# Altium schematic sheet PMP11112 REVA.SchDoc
size 431 x 558 mm; DocumentNumber: 1; SheetNumber: 1; SheetTotal: 1; PageSetup: Record=PageOptions¦CenterHorizontal=True¦CenterVertical=True¦PrintScale=0.49¦XCorrection=1.00¦YCorrection=1.00¦PrintKind=1¦BorderSize=5000000¦LeftOffset=0¦BottomOffset=0¦Orientation=2¦PaperLength=4318¦PaperWidth=2794¦Scale=100¦PaperSource=15¦PrintQuality=600¦MediaType=1¦DitherType=10¦PrintScaleMode=1¦PaperKind=Tabloid (11 x 17")¦PaperIndex=17
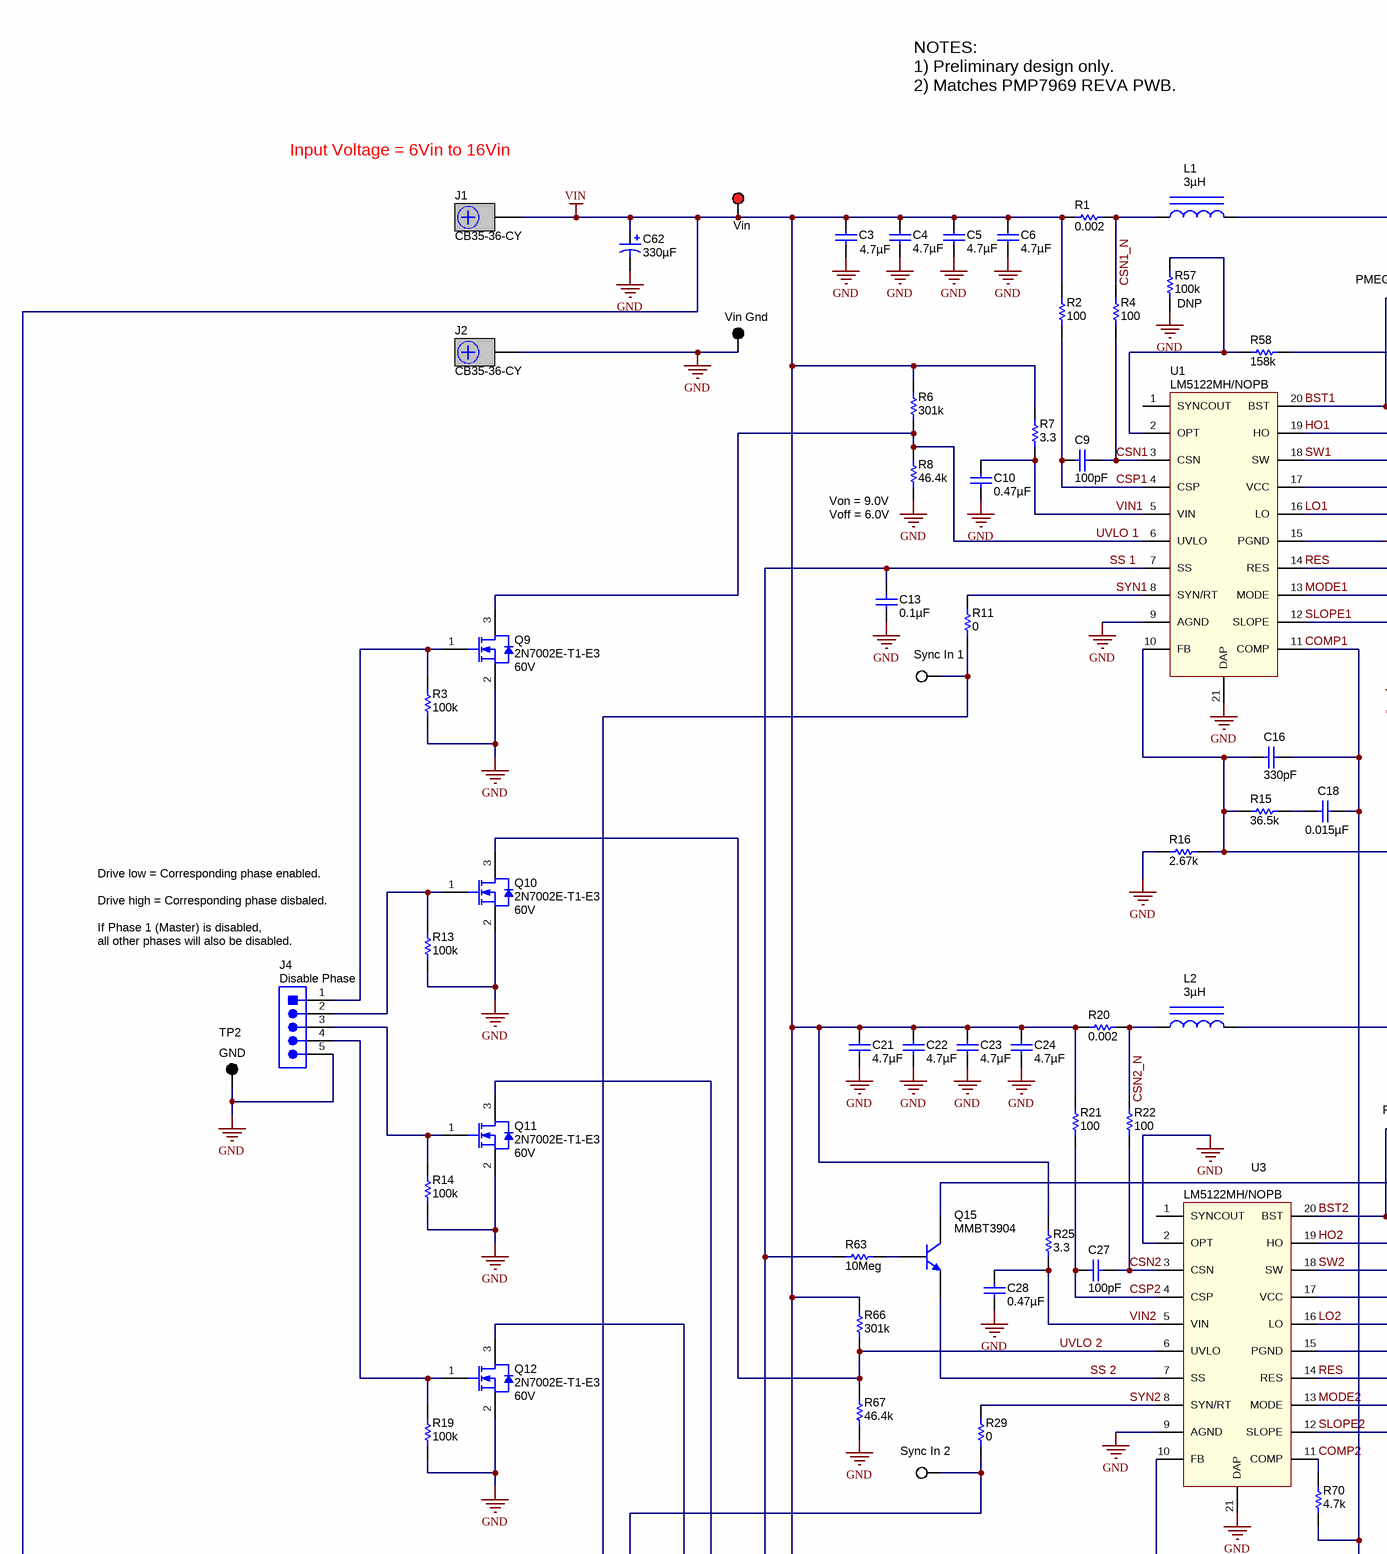
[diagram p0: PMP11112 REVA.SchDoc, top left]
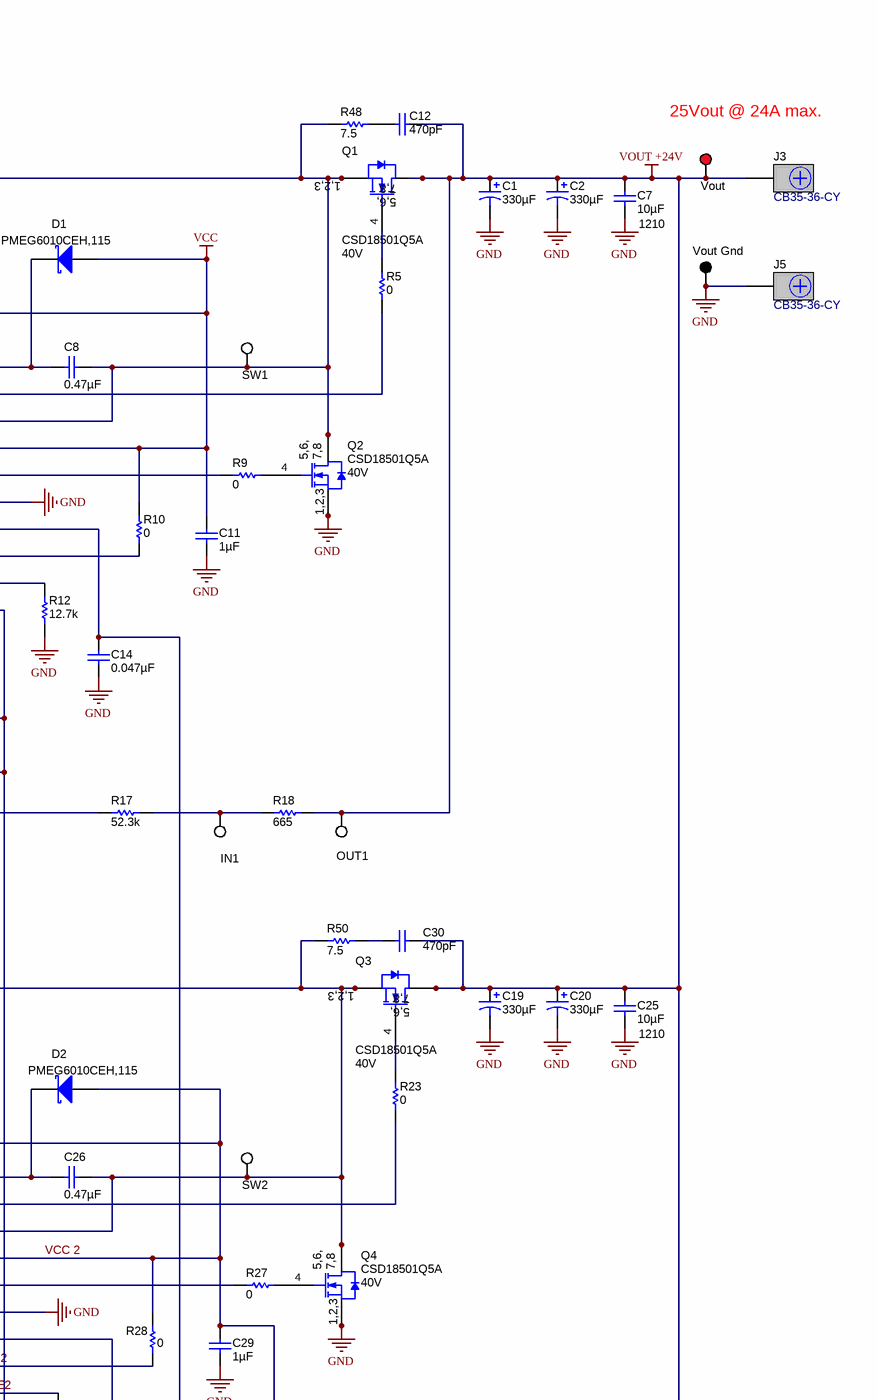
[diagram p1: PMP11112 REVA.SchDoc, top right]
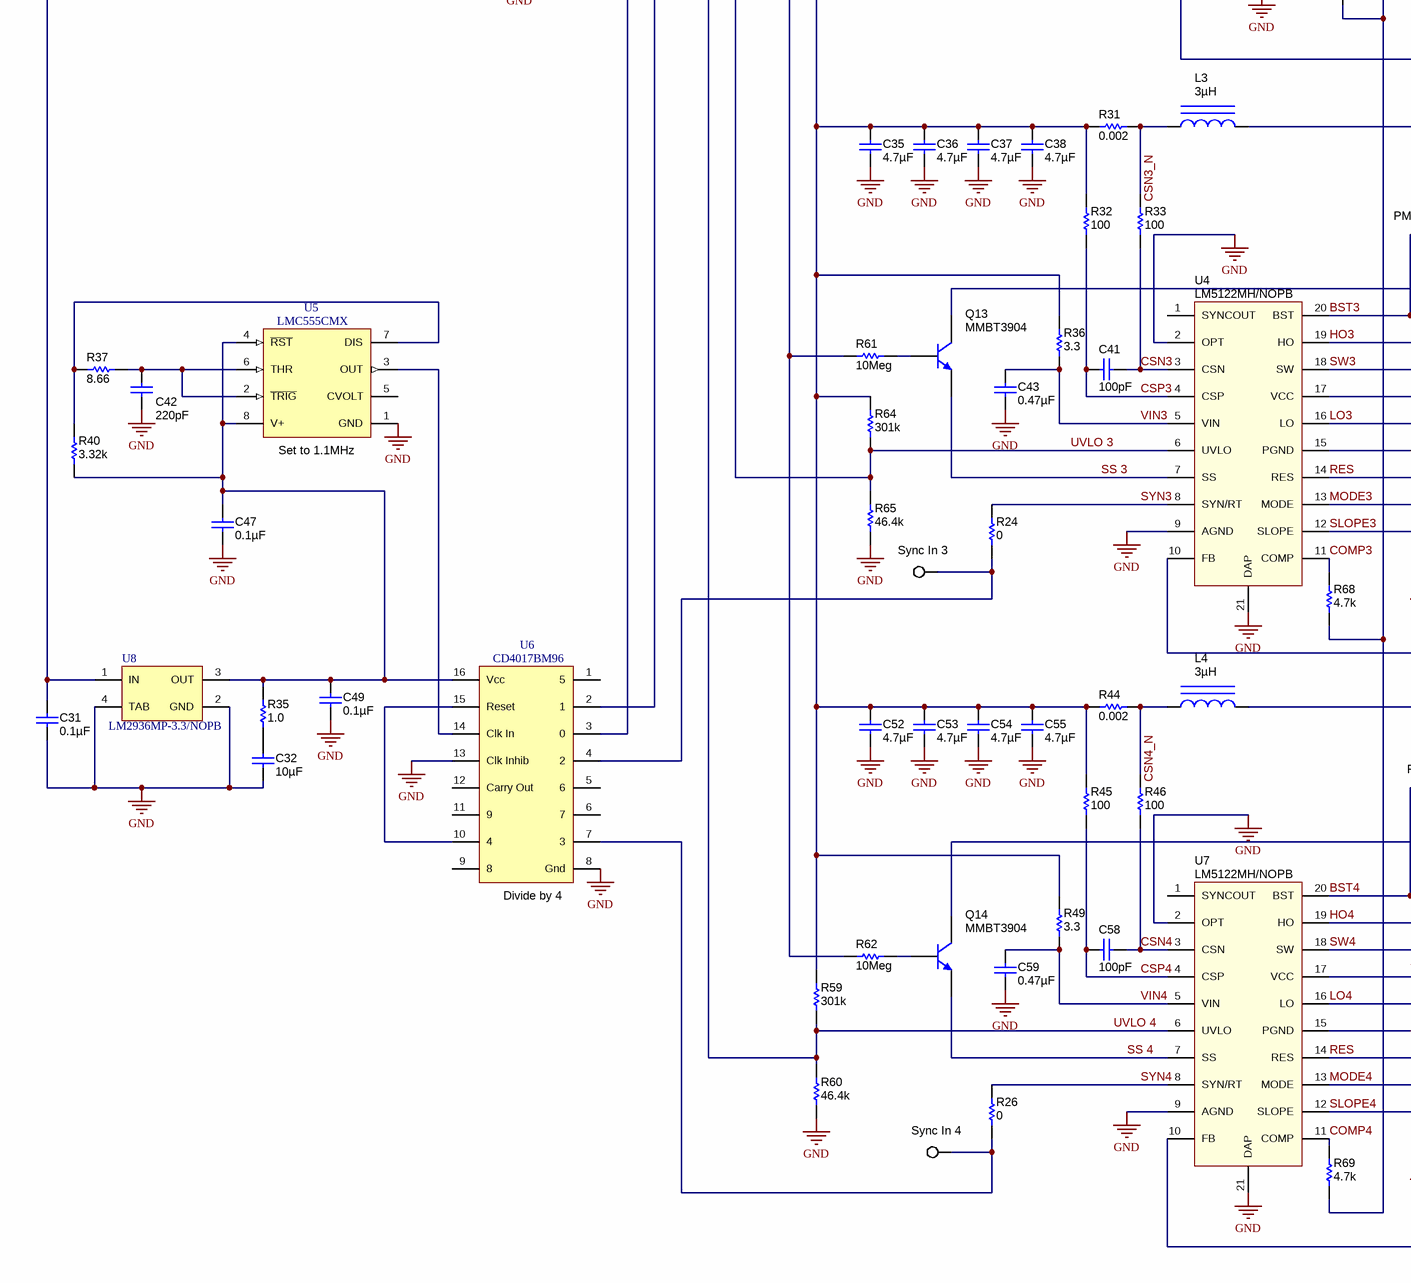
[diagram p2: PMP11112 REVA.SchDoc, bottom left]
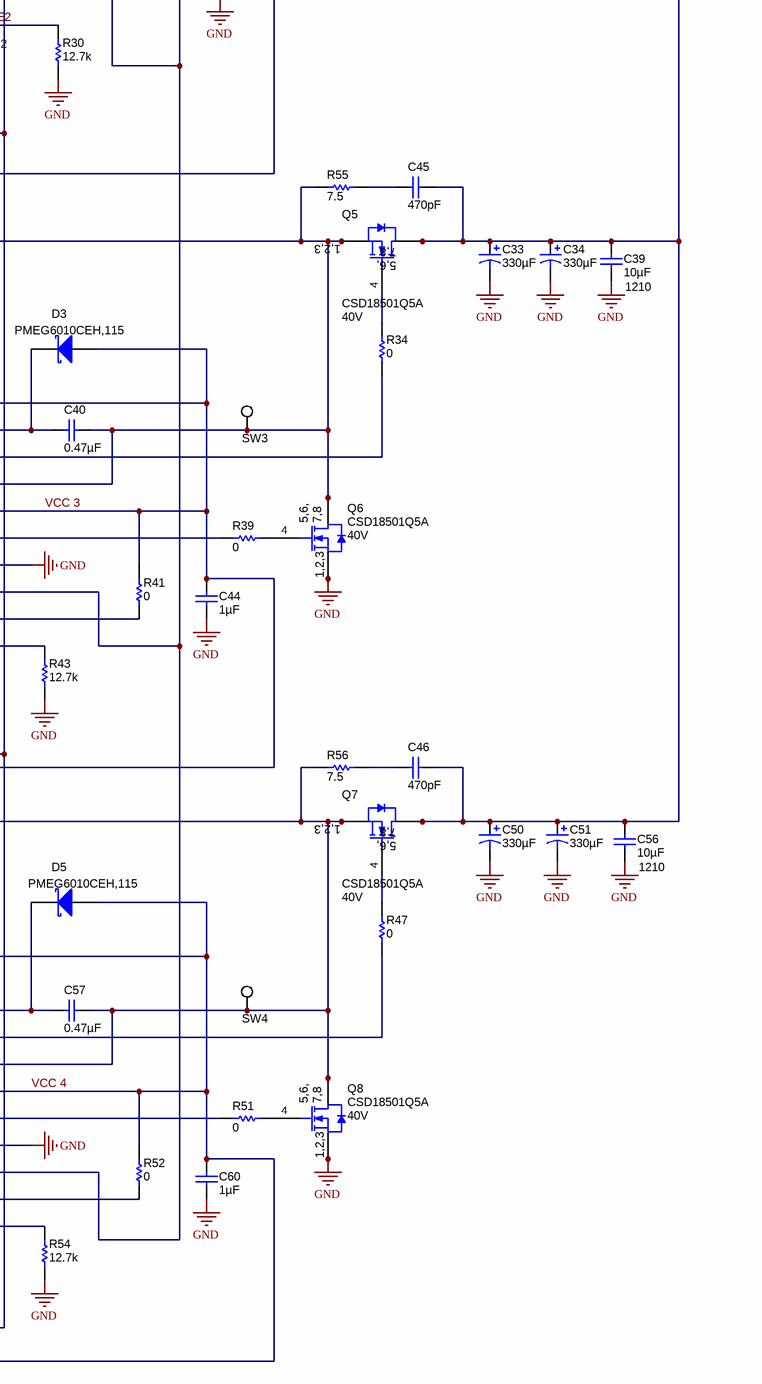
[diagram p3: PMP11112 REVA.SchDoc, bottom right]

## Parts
C1  ValueDisplayed: 330µF  [SM_RADIAL_G]  (hidden comment: EEE-FP1V331AP)
C2  ValueDisplayed: 330µF  [SM_RADIAL_G]  (hidden comment: EEE-FP1V331AP)
C3  ValueDisplayed: 4.7µF  [1206]  (hidden comment: GRM31CR71H475KA12L)
C4  ValueDisplayed: 4.7µF  [1206]  (hidden comment: GRM31CR71H475KA12L)
C5  ValueDisplayed: 4.7µF  [1206]  (hidden comment: GRM31CR71H475KA12L)
C6  ValueDisplayed: 4.7µF  [1206]  (hidden comment: GRM31CR71H475KA12L)
C7  ValueDisplayed: 10µF  [1210]  (hidden comment: GRM32ER7YA106KA12L)
C8  ValueDisplayed: 0.47µF  [0603_HV]  (hidden comment: GRM188R71E474KA12D)
C9  ValueDisplayed: 100pF  [0603_HV]  (hidden comment: GRM1885C1H101JA01D)
C10  ValueDisplayed: 0.47µF  [0603_HV]  (hidden comment: GRM188R71E474KA12D)
C11  ValueDisplayed: 1µF  [0603_HV]  (hidden comment: GRM188R71E105KA12D)
C12  ValueDisplayed: 470pF  [0805_HV]  (hidden comment: GRM2165C2A471JA01D)
C13  ValueDisplayed: 0.1µF  [0603_HV]  (hidden comment: GRM188R71E104KA01D)
C14  ValueDisplayed: 0.047µF  [0603_HV]  (hidden comment: GRM188R71E473KA01D)
C16  ValueDisplayed: 330pF  [0603_HV]  (hidden comment: GRM1885C1H331JA01D)
C18  ValueDisplayed: 0.015µF  [0603_HV]  (hidden comment: C1608X8R2A153K)
C19  ValueDisplayed: 330µF  [SM_RADIAL_G]  (hidden comment: EEE-FP1V331AP)
C20  ValueDisplayed: 330µF  [SM_RADIAL_G]  (hidden comment: EEE-FP1V331AP)
C21  ValueDisplayed: 4.7µF  [1206]  (hidden comment: GRM31CR71H475KA12L)
C22  ValueDisplayed: 4.7µF  [1206]  (hidden comment: GRM31CR71H475KA12L)
C23  ValueDisplayed: 4.7µF  [1206]  (hidden comment: GRM31CR71H475KA12L)
C24  ValueDisplayed: 4.7µF  [1206]  (hidden comment: GRM31CR71H475KA12L)
C25  ValueDisplayed: 10µF  [1210]  (hidden comment: GRM32ER7YA106KA12L)
C26  ValueDisplayed: 0.47µF  [0603_HV]  (hidden comment: GRM188R71E474KA12D)
C27  ValueDisplayed: 100pF  [0603_HV]  (hidden comment: GRM1885C1H101JA01D)
C28  ValueDisplayed: 0.47µF  [0603_HV]  (hidden comment: GRM188R71E474KA12D)
C29  ValueDisplayed: 1µF  [0603_HV]  (hidden comment: GRM188R71E105KA12D)
C30  ValueDisplayed: 470pF  [0805_HV]  (hidden comment: GRM2165C2A471JA01D)
C31  ValueDisplayed: 0.1µF  [0603]  (hidden comment: GCM188R71H104KA57D)
C32  ValueDisplayed: 10µF  [0805_HV]  (hidden comment: GRM21BR71A106KE51L)
C33  ValueDisplayed: 330µF  [SM_RADIAL_G]  (hidden comment: EEE-FP1V331AP)
C34  ValueDisplayed: 330µF  [SM_RADIAL_G]  (hidden comment: EEE-FP1V331AP)
C35  ValueDisplayed: 4.7µF  [1206]  (hidden comment: GRM31CR71H475KA12L)
C36  ValueDisplayed: 4.7µF  [1206]  (hidden comment: GRM31CR71H475KA12L)
C37  ValueDisplayed: 4.7µF  [1206]  (hidden comment: GRM31CR71H475KA12L)
C38  ValueDisplayed: 4.7µF  [1206]  (hidden comment: GRM31CR71H475KA12L)
C39  ValueDisplayed: 10µF  [1210]  (hidden comment: GRM32ER7YA106KA12L)
C40  ValueDisplayed: 0.47µF  [0603_HV]  (hidden comment: GRM188R71E474KA12D)
C41  ValueDisplayed: 100pF  [0603_HV]  (hidden comment: GRM1885C1H101JA01D)
C42  ValueDisplayed: 220pF  [0603]  (hidden comment: C1608C0G1H221J)
C43  ValueDisplayed: 0.47µF  [0603_HV]  (hidden comment: GRM188R71E474KA12D)
C44  ValueDisplayed: 1µF  [0603_HV]  (hidden comment: GRM188R71E105KA12D)
C45  ValueDisplayed: 470pF  [0805_HV]  (hidden comment: GRM2165C2A471JA01D)
C46  ValueDisplayed: 470pF  [0805_HV]  (hidden comment: GRM2165C2A471JA01D)
C47  ValueDisplayed: 0.1µF  [0603_HV]  (hidden comment: GRM188R71E104KA01D)
C49  ValueDisplayed: 0.1µF  [0603_HV]  (hidden comment: GRM188R71E104KA01D)
C50  ValueDisplayed: 330µF  [SM_RADIAL_G]  (hidden comment: EEE-FP1V331AP)
C51  ValueDisplayed: 330µF  [SM_RADIAL_G]  (hidden comment: EEE-FP1V331AP)
C52  ValueDisplayed: 4.7µF  [1206]  (hidden comment: GRM31CR71H475KA12L)
C53  ValueDisplayed: 4.7µF  [1206]  (hidden comment: GRM31CR71H475KA12L)
C54  ValueDisplayed: 4.7µF  [1206]  (hidden comment: GRM31CR71H475KA12L)
C55  ValueDisplayed: 4.7µF  [1206]  (hidden comment: GRM31CR71H475KA12L)
C56  ValueDisplayed: 10µF  [1210]  (hidden comment: GRM32ER7YA106KA12L)
C57  ValueDisplayed: 0.47µF  [0603_HV]  (hidden comment: GRM188R71E474KA12D)
C58  ValueDisplayed: 100pF  [0603_HV]  (hidden comment: GRM1885C1H101JA01D)
C59  ValueDisplayed: 0.47µF  [0603_HV]  (hidden comment: GRM188R71E474KA12D)
C60  ValueDisplayed: 1µF  [0603_HV]  (hidden comment: GRM188R71E105KA12D)
C62  ValueDisplayed: 330µF  [SM_RADIAL_G]  (hidden comment: EEE-FP1V331AP)
D1  PMEG6010CEH,115  [SOD-123F]
D2  PMEG6010CEH,115  [SOD-123F]
D3  PMEG6010CEH,115  [SOD-123F]
D5  PMEG6010CEH,115  [SOD-123F]
IN1  5007  [Keystone5007]  (value not drawn)
J1  CB35-36-CY  [CB35-36-CY]
J2  CB35-36-CY  [CB35-36-CY]
J3  CB35-36-CY  [CB35-36-CY]
J4  Disable Phase  [TSW-105-07-G-S]
J5  CB35-36-CY  [CB35-36-CY]
L1  ValueDisplayed: 3µH  [XAL1580]  (hidden comment: XAL1580-302MEB)
L2  ValueDisplayed: 3µH  [XAL1580]  (hidden comment: XAL1580-302MEB)
L3  ValueDisplayed: 3µH  [XAL1580]  (hidden comment: XAL1580-302MEB)
L4  ValueDisplayed: 3µH  [XAL1580]  (hidden comment: XAL1580-302MEB)
OUT1  5007  [Keystone5007]  (value not drawn)
Q1  CSD18501Q5A  value 40V  [Q5A WITH VIAS]
Q2  CSD18501Q5A  value 40V  [Q5A WITH VIAS]
Q3  CSD18501Q5A  value 40V  [Q5A WITH VIAS]
Q4  CSD18501Q5A  value 40V  [Q5A WITH VIAS]
Q5  CSD18501Q5A  value 40V  [Q5A WITH VIAS]
Q6  CSD18501Q5A  value 40V  [Q5A WITH VIAS]
Q7  CSD18501Q5A  value 40V  [Q5A WITH VIAS]
Q8  CSD18501Q5A  value 40V  [Q5A WITH VIAS]
Q9  2N7002E-T1-E3  value 60V  [SOT-23]
Q10  2N7002E-T1-E3  value 60V  [SOT-23]
Q11  2N7002E-T1-E3  value 60V  [SOT-23]
Q12  2N7002E-T1-E3  value 60V  [SOT-23]
Q13  MMBT3904  [SOT-23]
Q14  MMBT3904  [SOT-23]
Q15  MMBT3904  [SOT-23]
R1  ValueDisplayed: 0.002  [2512]  (hidden comment: CSNL2512FT2L00)
R2  ValueDisplayed: 100  [0603_HV]  (hidden comment: CRCW0603100RFKEA)
R3  value 100k  [0805_HV]  (hidden comment: CRCW0805100KFKEA)
R4  ValueDisplayed: 100  [0603_HV]  (hidden comment: CRCW0603100RFKEA)
R5  value 0  [0603_HV]  (hidden comment: ERJ-3GEY0R00V)
R6  ValueDisplayed: 301k  [0603_HV]  (hidden comment: CRCW0603301KFKEA)
R7  value 3.3  [0603_HV]  (hidden comment: CRCW06033R30JNEA)
R8  ValueDisplayed: 46.4k  [0603]  (hidden comment: RC0603FR-0746K4L)
R9  value 0  [0603_HV]  (hidden comment: ERJ-3GEY0R00V)
R10  value 0  [0603_HV]  (hidden comment: ERJ-3GEY0R00V)
R11  value 0  [0603]  (hidden comment: CRCW06030000Z0EA)
R12  ValueDisplayed: 12.7k  [0603_HV]  (hidden comment: CRCW060312K7FKEA)
R13  value 100k  [0805_HV]  (hidden comment: CRCW0805100KFKEA)
R14  value 100k  [0805_HV]  (hidden comment: CRCW0805100KFKEA)
R15  ValueDisplayed: 36.5k  [0603_HV]  (hidden comment: CRCW060336K5FKEA)
R16  value 2.67k  [0603_HV]  (hidden comment: CRCW06032K67FKEA)
R17  ValueDisplayed: 52.3k  [0805_HV]  (hidden comment: ERJ-6ENF5232V)
R18  ValueDisplayed: 665  [0805_HV]  (hidden comment: CRCW0805665RFKEA)
R19  value 100k  [0805_HV]  (hidden comment: CRCW0805100KFKEA)
R20  ValueDisplayed: 0.002  [2512]  (hidden comment: CSNL2512FT2L00)
R21  ValueDisplayed: 100  [0603_HV]  (hidden comment: CRCW0603100RFKEA)
R22  ValueDisplayed: 100  [0603_HV]  (hidden comment: CRCW0603100RFKEA)
R23  value 0  [0603_HV]  (hidden comment: ERJ-3GEY0R00V)
R24  value 0  [0603]  (hidden comment: CRCW06030000Z0EA)
R25  value 3.3  [0603_HV]  (hidden comment: CRCW06033R30JNEA)
R26  value 0  [0603]  (hidden comment: CRCW06030000Z0EA)
R27  value 0  [0603_HV]  (hidden comment: ERJ-3GEY0R00V)
R28  value 0  [0603_HV]  (hidden comment: ERJ-3GEY0R00V)
R29  value 0  [0603]  (hidden comment: CRCW06030000Z0EA)
R30  ValueDisplayed: 12.7k  [0603_HV]  (hidden comment: CRCW060312K7FKEA)
R31  ValueDisplayed: 0.002  [2512]  (hidden comment: CSNL2512FT2L00)
R32  ValueDisplayed: 100  [0603_HV]  (hidden comment: CRCW0603100RFKEA)
R33  ValueDisplayed: 100  [0603_HV]  (hidden comment: CRCW0603100RFKEA)
R34  value 0  [0603_HV]  (hidden comment: ERJ-3GEY0R00V)
R35  value 1.0  [0603]  (hidden comment: CRCW06031R00JNEA)
R36  value 3.3  [0603_HV]  (hidden comment: CRCW06033R30JNEA)
R37  value 8.66  [0603]  (hidden comment: CRCW06038R66FKEA)
R39  value 0  [0603_HV]  (hidden comment: ERJ-3GEY0R00V)
R40  ValueDisplayed: 3.32k  [0603]  (hidden comment: CRCW06033K32FKEA)
R41  value 0  [0603_HV]  (hidden comment: ERJ-3GEY0R00V)
R43  ValueDisplayed: 12.7k  [0603_HV]  (hidden comment: CRCW060312K7FKEA)
R44  ValueDisplayed: 0.002  [2512]  (hidden comment: CSNL2512FT2L00)
R45  ValueDisplayed: 100  [0603_HV]  (hidden comment: CRCW0603100RFKEA)
R46  ValueDisplayed: 100  [0603_HV]  (hidden comment: CRCW0603100RFKEA)
R47  value 0  [0603_HV]  (hidden comment: ERJ-3GEY0R00V)
R48  value 7.5  [2010M]  (hidden comment: ERJ-12ZYJ7R5U)
R49  value 3.3  [0603_HV]  (hidden comment: CRCW06033R30JNEA)
R50  value 7.5  [2010M]  (hidden comment: ERJ-12ZYJ7R5U)
R51  value 0  [0603_HV]  (hidden comment: ERJ-3GEY0R00V)
R52  value 0  [0603_HV]  (hidden comment: ERJ-3GEY0R00V)
R54  ValueDisplayed: 12.7k  [0603_HV]  (hidden comment: CRCW060312K7FKEA)
R55  value 7.5  [2010M]  (hidden comment: ERJ-12ZYJ7R5U)
R56  value 7.5  [2010M]  (hidden comment: ERJ-12ZYJ7R5U)
R57  DNP  value 100k  [0603]
R58  value 158k  [0603]  (hidden comment: CRCW0603158KFKEA)
R59  ValueDisplayed: 301k  [0603_HV]  (hidden comment: CRCW0603301KFKEA)
R60  ValueDisplayed: 46.4k  [0603]  (hidden comment: RC0603FR-0746K4L)
R61  value 10Meg  [0603]  (hidden comment: CRCW060310M0JNEA)
R62  value 10Meg  [0603]  (hidden comment: CRCW060310M0JNEA)
R63  value 10Meg  [0603]  (hidden comment: CRCW060310M0JNEA)
R64  ValueDisplayed: 301k  [0603_HV]  (hidden comment: CRCW0603301KFKEA)
R65  ValueDisplayed: 46.4k  [0603]  (hidden comment: RC0603FR-0746K4L)
R66  ValueDisplayed: 301k  [0603_HV]  (hidden comment: CRCW0603301KFKEA)
R67  ValueDisplayed: 46.4k  [0603]  (hidden comment: RC0603FR-0746K4L)
R68  value 4.7k  [0603]  (hidden comment: CRCW06034K70JNEA)
R69  value 4.7k  [0603]  (hidden comment: CRCW06034K70JNEA)
R70  value 4.7k  [0603]  (hidden comment: CRCW06034K70JNEA)
SW1  5002  [Keystone5002]  (value not drawn)
SW2  5002  [Keystone5002]  (value not drawn)
SW3  5002  [Keystone5002]  (value not drawn)
SW4  5002  [Keystone5002]  (value not drawn)
Sync_In_1  5007  [Keystone5007]  (value not drawn)
Sync_In_2  5007  [Keystone5007]  (value not drawn)
Sync_In_3  5007  [Keystone5007]  (value not drawn)
Sync_In_4  5007  [Keystone5007]  (value not drawn)
TP2  GND  [Keystone5006]
U1  LM5122MH/NOPB  [MXA20A_L - 10milVia]
U3  LM5122MH/NOPB  [MXA20A_L - 10milVia]
U4  LM5122MH/NOPB  [MXA20A_L - 10milVia]
U5  LMC555CMX  [M08A_N]
U6  CD4017BM96  [D (R-PDSO-G16)]
U7  LM5122MH/NOPB  [MXA20A_L - 10milVia]
U8  LM2936MP-3.3/NOPB  [MP04A_N]
Vin  5000  [Keystone5000]  (value not drawn)
Vin_Gnd  5001  [Keystone5001]  (value not drawn)
Vout  5000  [Keystone5000]  (value not drawn)
Vout_Gnd  5001  [Keystone5001]  (value not drawn)

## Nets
GND: C1.2(-) C2.2(-) C3.2 C4.2 C5.2 C6.2 C7.2 C10.2 C11.2 C13.2 C14.2 C19.2(-) C20.2(-) C21.2 C22.2 C23.2 C24.2 C25.2 C28.2 C29.2 C31.2 C32.2 C33.2(-) C34.2(-) C35.2 C36.2 C37.2 C38.2 C39.2 C42.2 C43.2 C44.2 C47.2 C49.2 C50.2(-) C51.2(-) C52.2 C53.2 C54.2 C55.2 C56.2 C59.2 C60.2 C62.2(-) J2.1 J4.5 J5.1 Q2.1(S) Q2.2(S) Q2.3(S) Q4.1(S) Q4.2(S) Q4.3(S) Q6.1(S) Q6.2(S) Q6.3(S) Q8.1(S) Q8.2(S) Q8.3(S) Q9.2(S) Q10.2(S) Q11.2(S) Q12.2(S) R3.1 R8.1 R12.1 R13.1 R14.1 R16.2 R19.1 R30.1 R43.1 R54.1 R57.1 R60.1 R65.1 R67.1 TP2.1 U1.9(AGND) U1.15(PGND) U1.21(DAP) U3.2(OPT) U3.9(AGND) U3.15(PGND) U3.21(DAP) U4.2(OPT) U4.9(AGND) U4.15(PGND) U4.21(DAP) U5.1(GND) U6.8(Gnd) U6.13(Clk_Inhib) U7.2(OPT) U7.9(AGND) U7.15(PGND) U7.21(DAP) U8.2(GND) U8.4(TAB) Vin_Gnd.1 Vout_Gnd.1
VCC: C11.1 D1.2(A) R10.2 R58.2 U1.17(VCC)
VIN: C3.1 C4.1 C5.1 C6.1 C21.1 C22.1 C23.1 C24.1 C31.1 C35.1 C36.1 C37.1 C38.1 C52.1 C53.1 C54.1 C55.1 C62.1(+) J1.1 R1.1 R2.2 R6.2 R7.2 R20.1 R21.2 R25.2 R31.1 R32.2 R36.2 R44.1 R45.2 R49.2 R59.2 R64.2 R66.2 U8.1(IN) Vin.1
VOUT +24V: C1.1(+) C2.1(+) C7.1 C12.1 C19.1(+) C20.1(+) C25.1 C30.1 C33.1(+) C34.1(+) C39.1 C45.1 C46.1 C50.1(+) C51.1(+) C56.1 J3.1 OUT1.1 Q1.5(D) Q1.6(D) Q1.7(D) Q1.8(D) Q1.9(D) Q3.5(D) Q3.6(D) Q3.7(D) Q3.8(D) Q3.9(D) Q5.5(D) Q5.6(D) Q5.7(D) Q5.8(D) Q5.9(D) Q7.5(D) Q7.6(D) Q7.7(D) Q7.8(D) Q7.9(D) R18.1 Vout.1
BST1: C8.2 D1.1(K) U1.20(BST)
BST2: C26.2 D2.1(K) U3.20(BST)
BST3: C40.2 D3.1(K) U4.20(BST)
BST4: C57.2 D5.1(K) U7.20(BST)
COMP1: C16.2 C18.2 R68.1 R69.1 R70.1 U1.11(COMP)
COMP2: R70.2 U3.11(COMP)
COMP3: R68.2 U4.11(COMP)
COMP4: R69.2 U7.11(COMP)
CSN1: C9.1 R4.1 U1.3(CSN)
CSN1_N: L1.1 R1.2 R4.2
CSN2: C27.1 R22.1 U3.3(CSN)
CSN2_N: L2.1 R20.2 R22.2
CSN3: C41.1 R33.1 U4.3(CSN)
CSN3_N: L3.1 R31.2 R33.2
CSN4: C58.1 R46.1 U7.3(CSN)
CSN4_N: L4.1 R44.2 R46.2
CSP1: C9.2 R2.1 U1.4(CSP)
CSP2: C27.2 R21.1 U3.4(CSP)
CSP3: C41.2 R32.1 U4.4(CSP)
CSP4: C58.2 R45.1 U7.4(CSP)
HO1: R5.2 U1.19(HO)
HO2: R23.2 U3.19(HO)
HO3: R34.2 U4.19(HO)
HO4: R47.2 U7.19(HO)
LO1: R9.2 U1.16(LO)
LO2: R27.2 U3.16(LO)
LO3: R39.2 U4.16(LO)
LO4: R51.2 U7.16(LO)
MODE1: R10.1 U1.13(MODE)
MODE2: R28.1 U3.13(MODE)
MODE3: R41.1 U4.13(MODE)
MODE4: R52.1 U7.13(MODE)
RES: C14.1 U1.14(RES) U3.14(RES) U4.14(RES) U7.14(RES)
SLOPE1: R12.2 U1.12(SLOPE)
SLOPE2: R30.2 U3.12(SLOPE)
SLOPE3: R43.2 U4.12(SLOPE)
SLOPE4: R54.2 U7.12(SLOPE)
SS 1: C13.1 R61.1 R62.1 R63.1 U1.7(SS)
SS 2: Q15.2(E) U3.7(SS)
SS 3: Q13.2(E) U4.7(SS)
SS 4: Q14.2(E) U7.7(SS)
SW1: C8.1 L1.2 Q1.1(S) Q1.2(S) Q1.3(S) Q2.5(D) Q2.6(D) Q2.7(D) Q2.8(D) Q2.9(D) R48.2 SW1.1 U1.18(SW)
SW2: C26.1 L2.2 Q3.1(S) Q3.2(S) Q3.3(S) Q4.5(D) Q4.6(D) Q4.7(D) Q4.8(D) Q4.9(D) R50.2 SW2.1 U3.18(SW)
SW3: C40.1 L3.2 Q5.1(S) Q5.2(S) Q5.3(S) Q6.5(D) Q6.6(D) Q6.7(D) Q6.8(D) Q6.9(D) R55.2 SW3.1 U4.18(SW)
SW4: C57.1 L4.2 Q7.1(S) Q7.2(S) Q7.3(S) Q8.5(D) Q8.6(D) Q8.7(D) Q8.8(D) Q8.9(D) R56.2 SW4.1 U7.18(SW)
SYN1: R11.1 U1.8(SYN/RT)
SYN2: R29.1 U3.8(SYN/RT)
SYN3: R24.1 U4.8(SYN/RT)
SYN4: R26.1 U7.8(SYN/RT)
UVLO 1: Q9.3(D) R6.1 R8.2 U1.6(UVLO)
UVLO 2: Q10.3(D) R66.1 R67.2 U3.6(UVLO)
UVLO 3: Q11.3(D) R64.1 R65.2 U4.6(UVLO)
UVLO 4: Q12.3(D) R59.1 R60.2 U7.6(UVLO)
VCC 2: C29.1 D2.2(A) Q15.3(C) R28.2 U3.10(FB) U3.17(VCC)
VCC 3: C44.1 D3.2(A) Q13.3(C) R41.2 U4.10(FB) U4.17(VCC)
VCC 4: C60.1 D5.2(A) Q14.3(C) R52.2 U7.10(FB) U7.17(VCC)
VIN1: C10.1 R7.1 U1.5(VIN)
VIN2: C28.1 R25.1 U3.5(VIN)
VIN3: C43.1 R36.1 U4.5(VIN)
VIN4: C59.1 R49.1 U7.5(VIN)
NetC12_2: C12.2 R48.1
NetC16_1: C16.1 R15.1 R16.1 R17.1 U1.10(FB)
NetC18_1: C18.1 R15.2
NetC30_2: C30.2 R50.1
NetC32_1: C32.1 R35.1
NetC42_1: C42.1 R37.1 U5.2(~{TRIG}) U5.6(THR)
NetC45_2: C45.2 R55.1
NetC46_2: C46.2 R56.1
NetC47_1: C47.1 C49.1 R35.2 R40.1 U5.4(~{RST}) U5.8(V+) U6.16(Vcc) U8.3(OUT)
NetIN1_1: IN1.1 R17.2 R18.2
NetJ4_1: J4.1 Q9.1(G) R3.2
NetJ4_2: J4.2 Q10.1(G) R13.2
NetJ4_3: J4.3 Q11.1(G) R14.2
NetJ4_4: J4.4 Q12.1(G) R19.2
NetQ1_4: Q1.4(G) R5.1
NetQ2_4: Q2.4(G) R9.1
NetQ3_4: Q3.4(G) R23.1
NetQ4_4: Q4.4(G) R27.1
NetQ5_4: Q5.4(G) R34.1
NetQ6_4: Q6.4(G) R39.1
NetQ7_4: Q7.4(G) R47.1
NetQ8_4: Q8.4(G) R51.1
NetQ13_1: Q13.1(B) R61.2
NetQ14_1: Q14.1(B) R62.2
NetQ15_1: Q15.1(B) R63.2
NetR11_2: R11.2 Sync_In_1.1 U6.3(0)
NetR24_2: R24.2 Sync_In_3.1 U6.4(2)
NetR26_2: R26.2 Sync_In_4.1 U6.7(3)
NetR29_2: R29.2 Sync_In_2.1 U6.2(1)
NetR37_2: R37.2 R40.2 U5.7(DIS)
NetR57_2: R57.2 R58.1 U1.2(OPT)
NetU5_3: U5.3(OUT) U6.14(Clk_In)
NetU6_10: U6.10(4) U6.15(Reset)

Not connected (* = marked no-connect by the designer): U1 1(SYNCOUT); U3 1(SYNCOUT); U4 1(SYNCOUT); U5 5(CVOLT); U6 1(5) 5(6) 6(7) 9(8) 11(9) 12(Carry_Out); U7 1(SYNCOUT)

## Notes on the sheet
- Input Voltage = 6Vin to 16Vin
- NOTES:
  1) Preliminary design only.
  2) Matches PMP7969 REVA PWB.
- 25Vout @ 24A max.
- (near R8) Von = 9.0V
- (near R8) Voff = 6.0V
- (near J4) Drive low = Corresponding phase enabled.
  Drive high = Corresponding phase disbaled.
  If Phase 1 (Master) is disabled,
  all other phases will also be disabled.
- (near U5) Set to 1.1MHz
- (near U6) Divide by 4

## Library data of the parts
C1 C2 C19 C20 C33 C34 C50 C51 C62 = EEE-FP1V331AP: CAP ALUM 330UF 35V 20% SMD; Manufacturer: Panasonic; Polarized: Y; CompType: Capacitor; U/M: EA; Cap_F: 0.00033; Tolerance_%: 20; Value1: 0.06 ohm; VDC_V: 35; ESR_Ohm: 0.06; IRMS_A: 1.19; TaMin_C: -55; TaMax_C: 105; Cap_Case: G
C3-C6 C21-C24 C35-C38 C52-C55 = GRM31CR71H475KA12L: CAP, CERM, 4.7uF, 50V, +/-10%, X7R, 1206; Manufacturer: MuRata; Polarized: N; CompType: Capacitor; U/M: EA; Cap_F: 0.0000047; Tolerance_%: 10; VDC_V: 50; TaMin_C: -55; TaMax_C: 125; Cap_Case: 2220
C7 C25 C39 C56 = GRM32ER7YA106KA12L: CAP, CERM, 10uF, 35V, +/-10%, X7R, 1210; Manufacturer: MuRata; Polarized: N; CompType: Capacitor; U/M: EA; Cap_F: 0.00001; Tolerance_%: 10; VDC_V: 35; TaMin_C: -55; TaMax_C: 125
C8 C10 C26 C28 C40 C43 C57 C59 = GRM188R71E474KA12D: CAP, CERM, 0.47uF, 25V, +/-10%, X7R, 0603; Manufacturer: MuRata; Polarized: N; CompType: Capacitor; U/M: EA; Cap_F: 0.00000047; Tolerance_%: 10; VDC_V: 25; TaMin_C: -55; TaMax_C: 125; Cap_Case: 0603
C9 C27 C41 C58 = GRM1885C1H101JA01D: CAP, CERM, 100pF, 50V, +/-5%, C0G/NP0, 0603; Manufacturer: MuRata; Polarized: N; CompType: Capacitor; U/M: EA; Cap_F: 0.0000000001; Tolerance_%: 5; VDC_V: 50; TaMin_C: -55; TaMax_C: 125; Cap_Case: 0603
C11 C29 C44 C60 = GRM188R71E105KA12D: CAP, CERM, 1uF, 25V, +/-10%, X7R, 0603; Manufacturer: MuRata; Polarized: N; CompType: Capacitor; U/M: EA; Cap_F: 0.000001; Tolerance_%: 10; VDC_V: 25; TaMin_C: -55; TaMax_C: 125; Cap_Case: 0603
C12 C30 C45 C46 = GRM2165C2A471JA01D: CAP, CERM, 470pF, 100V, +/-5%, C0G/NP0, 0805; Manufacturer: MuRata; Polarized: N; CompType: Capacitor; U/M: EA; Cap_F: 0.00000000047; Tolerance_%: 5; VDC_V: 100; TaMin_C: -55; TaMax_C: 125; Cap_Case: 0805
C13 C47 C49 = GRM188R71E104KA01D: CAP, CERM, 0.1uF, 25V, +/-10%, X7R, 0603; Manufacturer: MuRata; Polarized: N; CompType: Capacitor; U/M: EA; Cap_F: 0.0000001; Tolerance_%: 10; VDC_V: 25; TaMin_C: -55; TaMax_C: 125; Cap_Case: 0603
C14 = GRM188R71E473KA01D: CAP, CERM, 0.047uF, 25V, +/-10%, X7R, 0603; Manufacturer: MuRata; Polarized: N; CompType: Capacitor; U/M: EA; Cap_F: 0.000000047; Tolerance_%: 10; VDC_V: 25; TaMin_C: -55; TaMax_C: 125; Cap_Case: 0603
C16 = GRM1885C1H331JA01D: CAP, CERM, 330 pF, 50 V, +/- 5%, C0G/NP0, 0603; Manufacturer: MuRata; Polarized: N; CompType: Capacitor; Value: 330pF; U/M: EA; Cap_F: 0.00000000033; Tolerance_%: 5; Value1: Unknown; VDC_V: 50; Value2: 50V; TaMin_C: -55; TaMax_C: 125; Cap_Case: 0603
C18 = C1608X8R2A153K: CAP, CERM, 0.015 µF, 100 V, +/- 10%, X8R, 0603; Manufacturer: TDK; Polarized: N; CompType: Capacitor; Value: 0.015uF; U/M: EA; Cap_F: 0.000000015; Tolerance_%: 10; ESR_ohm: 0.0391; Value1: 0.0391 ohm; VDC_V: 100; Value2: 100V; TaMin_C: -55; TaMax_C: 150; Cap_Case: 0603
C31 = GCM188R71H104KA57D: CAP, CERM, 0.1uF, 50V, +/-10%, X7R, 0603; Manufacturer: MuRata; Polarized: N; CompType: Capacitor; U/M: EA; Cap_F: 0.0000001; Tolerance_%: 10; ESR_Ohm: 0.02; Value1: 0.02 ohm; VDC_V: 50; IRMS_A: 1.84; TaMin_C: -55; TaMax_C: 125
C32 = GRM21BR71A106KE51L: CAP, CERM, 10uF, 10V, +/-10%, X7R, 0805; Manufacturer: MuRata; Polarized: N; CompType: Capacitor; U/M: EA; Cap_F: 0.00001; Tolerance_%: 10; ESR_Ohm: 0.003; Value1: 0.003 ohm; TaMin_C: -55; TaMax_C: 125; Cap_Case: 0805
C42 = C1608C0G1H221J: CAP, CERM, 220pF, 50V, +/-5%, C0G/NP0, 0603; Manufacturer: TDK; Polarized: N; CompType: Capacitor; U/M: EA; Cap_F: 0.00000000022; Tolerance_%: 5; ESR_Ohm: 0.0831; Value1: 0.0831 ohm; VDC_V: 50; TaMin_C: -55; TaMax_C: 125
D1-D3 D5 = PMEG6010CEH,115: Diode, Schottky, 60V, 1A, SOD-123F; Manufacturer: NXP Semiconductor; U/M: EA; Vf_V: 0.57; Io_A: 1; Vr_V: 60; TJmax_C: 150; Value: 0.57V
IN1 OUT1 Sync_In_1-Sync_In_4 = 5007: Test Point, TH, Compact, White; Manufacturer: Keystone; CompType: Test Point Loop; U/M: EA
J1 J2 = CB35-36-CY: Terminal 50A Lug; Manufacturer: Panduit; CompType: Screw Terminal; SymbolCreator: crossc; U/M: EA
J3 J5 = CB35-36-CY: Terminal 50A Lug; Manufacturer: Panduit; CompType: Screw Terminal; U/M: EA; SymbolCreator: crossc
J4 = TSW-105-07-G-S: Header, TH, 100mil, 5x1, Gold plated, 230 mil above insulator; Manufacturer: Samtec; SymbolCreator: a0412235; U/M: EA
L1-L4 = XAL1580-302MEB: Inductor, Shielded, Composite, 3 µH, 34.4 A, 0.002619 ohm, SMD; Manufacturer: Coilcraft; Value: 3uH; Ind_H: 3.0E-6; Imax_A: 34.4; Irms: 34.4A @ 40C rise; Isat: 43A @ 0.7% inductance drop; Value2: 34.4A
Q1-Q8 = CSD18501Q5A: MOSFET, N-CH, 40 V, 22 A, SON 5x6mm; Manufacturer: Texas Instruments; Alternate Manufacturer: None; U/M: EA; ChType: N; VdsMax_V: 40; Value1: 0.0043 ohm; Rdson45_Ohm: 0.0043; Value2: 20 nC; QgTyp_nC: 20; IdsMax_A: 22
Q9-Q12 = 2N7002E-T1-E3: MOSFET, N-CH, 60V, 0.24A, SOT-23; Manufacturer: Vishay-Siliconix; Alternate Manufacturer: None; U/M: EA; ChType: N; VdsMax_V: 60; Value1: 1.8 ohm; Rdson45_Ohm: 1.8; Value2: 0.4 nC; QgTyp_nC: 0.4; Vgs_V: 20; IdsMax_A: 0.24
Q13-Q15 = MMBT3904, Fairchild Semiconductor: Transistor, NPN, 40V, 0.2A, SOT-23; CompType: BJT; PNP: 0; NPN: 1; Vceo_V: 40; Vcesat1_V: 0.2; Value: 0.2V; HfeMax: 300; TaMin_C: -55; TaMax_C: 150; U/M: EA
R1 R20 R31 R44 = CSNL2512FT2L00: RES, 0.002, 1%, 2 W, 2512; Manufacturer: Stackpole Electronics Inc; CompType: Resistor; Value: 0.002; Value_Code: 2L000; Tolerance_%: 1; Power_W: 2; Value2: 2W; VDC_V: 200; TempCo: 50 ppm/C; U/M: EA
R2 R4 R21 R22 R32 R33 R45 R46 = CRCW0603100RFKEA: RES, 100, 1%, 0.1 W, 0603; Manufacturer: Vishay-Dale; CompType: Resistor; Value: 100; Value_Code: 100R; Tolerance_%: 1; Power_W: 0.1; Value2: 0.1W; VDC_V: 75; TempCo: 100 ppm/C; EIA_Code: E96; U/M: EA
R3 R13 R14 R19 = CRCW0805100KFKEA: RES, 100k ohm, 1%, 0.125W, 0805; Manufacturer: Vishay-Dale; CompType: Resistor; Res_ohm: 100000; Tolerance_%: 1; Power_W: 0.125; VDC_V: 150; TempCo: 100 ppm/C; EIA_Code: E96; U/M: EA
R5 R9 R10 R23 R27 R28 R34 R39 R41 R47 R51 R52 = ERJ-3GEY0R00V: RES, 0 ohm, 5%, 0.1W, 0603; Manufacturer: Panasonic; CompType: Resistor; Value_Code: 0000; Tolerance_%: 5; Power_W: 0.1; VDC_V: 50; TempCo: 600 ppm/C; EIA_Code: E24; U/M: EA
R6 R59 R64 R66 = CRCW0603301KFKEA: RES, 301 k, 1%, 0.1 W, 0603; Manufacturer: Vishay-Dale; CompType: Resistor; Value: 301k; Res_ohm: 301000; Tolerance_%: 1; Power_W: 0.1; Value2: 0.1W; VDC_V: 75; TempCo: 100 ppm/C; EIA_Code: E96; U/M: EA
R7 R25 R36 R49 = CRCW06033R30JNEA: RES, 3.3 ohm, 5%, 0.1W, 0603; Manufacturer: Vishay-Dale; CompType: Resistor; Value_Code: 3R30; Tolerance_%: 5; Power_W: 0.1; VDC_V: 75; TempCo: 200 ppm/C; EIA_Code: E24; U/M: EA
R8 R60 R65 R67 = RC0603FR-0746K4L: RES, 46.4 k, 1%, 0.1 W, 0603; Manufacturer: Yageo America; CompType: Resistor; Value: 46.4k; Res_ohm: 46400; Value_Code: 46k4; Tolerance_%: 1; Power_W: 0.1; Value2: 0.1W; VDC_V: 150; TempCo: 200 ppm/C; EIA_Code: E96; U/M: EA
R11 R24 R26 R29 = CRCW06030000Z0EA: RES, 0 ohm, 5%, 0.1W, 0603; Manufacturer: Vishay-Dale; CompType: Resistor; U/M: EA; Tolerance_%: 5; VDC_V: 75; TempCo: 200 ppm/C; Value_Code: 0000; Power_W: 0.1; EIA_Code: E24
R12 R30 R43 R54 = CRCW060312K7FKEA: RES, 12.7 k, 1%, 0.1 W, 0603; Manufacturer: Vishay-Dale; CompType: Resistor; Value: 12.7k; Res_ohm: 12700; Value_Code: 12k7; Tolerance_%: 1; Power_W: 0.1; Value2: 0.1W; VDC_V: 75; TempCo: 100 ppm/C; EIA_Code: E96; U/M: EA
R15 = CRCW060336K5FKEA: RES, 36.5 k, 1%, 0.1 W, 0603; Manufacturer: Vishay-Dale; CompType: Resistor; Value: 36.5k; Res_ohm: 36500; Value_Code: 36k5; Tolerance_%: 1; Power_W: 0.1; Value2: 0.1W; VDC_V: 75; TempCo: 100 ppm/C; EIA_Code: E96; U/M: EA
R16 = CRCW06032K67FKEA: RES, 2.67k ohm, 1%, 0.1W, 0603; Manufacturer: Vishay-Dale; CompType: Resistor; Res_ohm: 2670; Value_Code: 2k67; Tolerance_%: 1; Power_W: 0.1; VDC_V: 75; TempCo: 100 ppm/C; EIA_Code: E96; U/M: EA
R17 = ERJ-6ENF5232V: RES, 52.3 k, 1%, 0.125 W, 0805; Manufacturer: Panasonic; CompType: Resistor; Value: 52.3k; Res_ohm: 52300; Value_Code: 52k3; Tolerance_%: 1; Power_W: 0.125; Value2: 0.125W; TempCo: 100 ppm/C; EIA_Code: E96; U/M: EA
R18 = CRCW0805665RFKEA: RES, 665, 1%, 0.125 W, 0805; Manufacturer: Vishay-Dale; CompType: Resistor; Value: 665; Value_Code: 665R; Tolerance_%: 1; Power_W: 0.125; Value2: 0.125W; VDC_V: 150; TempCo: 100 ppm/C; EIA_Code: E96; U/M: EA
R35 = CRCW06031R00JNEA: RES, 1.0 ohm, 5%, 0.1W, 0603; Manufacturer: Vishay-Dale; CompType: Resistor; Res_ohm: 1; Value_Code: 1R00; Tolerance_%: 5; Power_W: 0.1; VDC_V: 75; TempCo: 200 ppm/C; EIA_Code: E24; U/M: EA
R37 = CRCW06038R66FKEA: RES, 8.66 ohm, 1%, 0.1W, 0603; Manufacturer: Vishay-Dale; CompType: Resistor; Value_Code: 8R66; Tolerance_%: 1; Power_W: 0.1; VDC_V: 75; TempCo: 100 ppm/C; EIA_Code: E96; U/M: EA
R40 = CRCW06033K32FKEA: RES, 3.32 k, 1%, 0.1 W, 0603; Manufacturer: Vishay-Dale; CompType: Resistor; Value: 3.32k; Res_ohm: 3320; Value_Code: 3k32; Tolerance_%: 1; Power_W: 0.1; Value2: 0.1W; VDC_V: 75; TempCo: 100 ppm/C; EIA_Code: E96; U/M: EA
R48 R50 R55 R56 = ERJ-12ZYJ7R5U: RESISTOR 7.5 OHM 3/4W 5% 2010; Manufacturer: Panasonic; Value_Code: 7R50; Tolerance_%: 5; Power_W: 1; Value2: 1W; VDC_V: 3; TempCo: -100 /+600 ppm/C; EIA_Code: E24; U/M: EA
R57 = CRCW0603100KFKEA: RES, 100k ohm, 1%, 0.1W, 0603; Manufacturer: Vishay-Dale; CompType: Resistor; Res_ohm: 100000; Tolerance_%: 1; Power_W: 0.1; VDC_V: 75; TempCo: 100 ppm/C; EIA_Code: E96; U/M: EA
R58 = CRCW0603158KFKEA: RES, 158k ohm, 1%, 0.1W, 0603; Manufacturer: Vishay-Dale; CompType: Resistor; Res_ohm: 158000; Tolerance_%: 1; Power_W: 0.1; VDC_V: 75; TempCo: 100 ppm/C; EIA_Code: E96; U/M: EA
R61-R63 = CRCW060310M0JNEA: RES, 10Meg ohm, 5%, 0.1W, 0603; Manufacturer: Vishay-Dale; CompType: Resistor; Res_ohm: 10000000; Value_Code: 10M0; Tolerance_%: 5; Power_W: 0.1; VDC_V: 75; TempCo: 200 ppm/C; EIA_Code: E24; U/M: EA
R68-R70 = CRCW06034K70JNEA: RES, 4.7k ohm, 5%, 0.1W, 0603; Manufacturer: Vishay-Dale; CompType: Resistor; Res_ohm: 4700; Value_Code: 4k70; Tolerance_%: 5; Power_W: 0.1; VDC_V: 75; TempCo: 200 ppm/C; EIA_Code: E24; U/M: EA
SW1-SW4 = 5002: Test Point, TH, Miniature, White; Manufacturer: Keystone; CompType: Test Point Loop; U/M: EA
TP2 = 5006: Test Point, Compact, Black, TH; Manufacturer: Keystone; CompType: Test Point Loop; U/M: EA
U1 U3 U4 U7 = LM5122MH/NOPB: Wide Input Synchronous Boost Controller with Multiple Phase Capability, PWP0020A; Manufacturer: Texas Instruments; SymbolCreator: a0411947; CompType: IC; U/M: EA
U5 = LMC555CMX: CMOS Timer, 8-pin Narrow SOIC; Manufacturer: Texas Instruments; PackageTopMarking: NSZXTT*LMC*555CM; CompType: Analog IC; PowerWise: N
U6 = CD4017BM96: IC 10-OUT DECADE COUNTER 16-SOIC; Manufacturer: Texas Instruments; CompType: MiscPower
U8 = LM2936MP-3.3/NOPB: Ultra-Low Quiescent Current LDO Voltage Regulator, 4-pin SOT-223, Pb-Free; Manufacturer: Texas Instruments; PackageTopMarking: XYTT*KABA; PowerWise: N; CompType: LDO IC
Vin Vout = 5000: Test Point, TH, Miniature, Red; Manufacturer: Keystone; CompType: Test Point Loop; U/M: EA
Vin_Gnd Vout_Gnd = 5001: Test Point, TH, Miniature, Black; Manufacturer: Keystone; CompType: Test Point Loop; U/M: EA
